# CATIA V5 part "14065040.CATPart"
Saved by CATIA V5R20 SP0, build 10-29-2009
Part number: 14065040
Definition: NONE
Nomenclature: 14065040
Source: Unknown
Description: 14065040
Bounding box of the stored display mesh (mm): x -20 to 80, y -46.5 to 36.6, z -36.6 to 36.6
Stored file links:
  C:\Users\Utente\Desktop\IO LAVORO\3D X SITO CF\X SITO\PLASTICA\RF2\14065040.CATPart
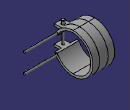
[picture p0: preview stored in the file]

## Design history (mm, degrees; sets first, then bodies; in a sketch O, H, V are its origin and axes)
Body1 "14065040" (main body)
  Solid1: solid without history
